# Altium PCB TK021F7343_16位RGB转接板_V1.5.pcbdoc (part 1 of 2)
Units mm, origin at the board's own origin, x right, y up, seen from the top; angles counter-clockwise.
Board outline 79.4 x 75.01 mm, 2 copper layers (Top Layer, Bottom Layer), stack 0.07 mm thick; 14 components, 33 nets, 105 pads, 145 vias.
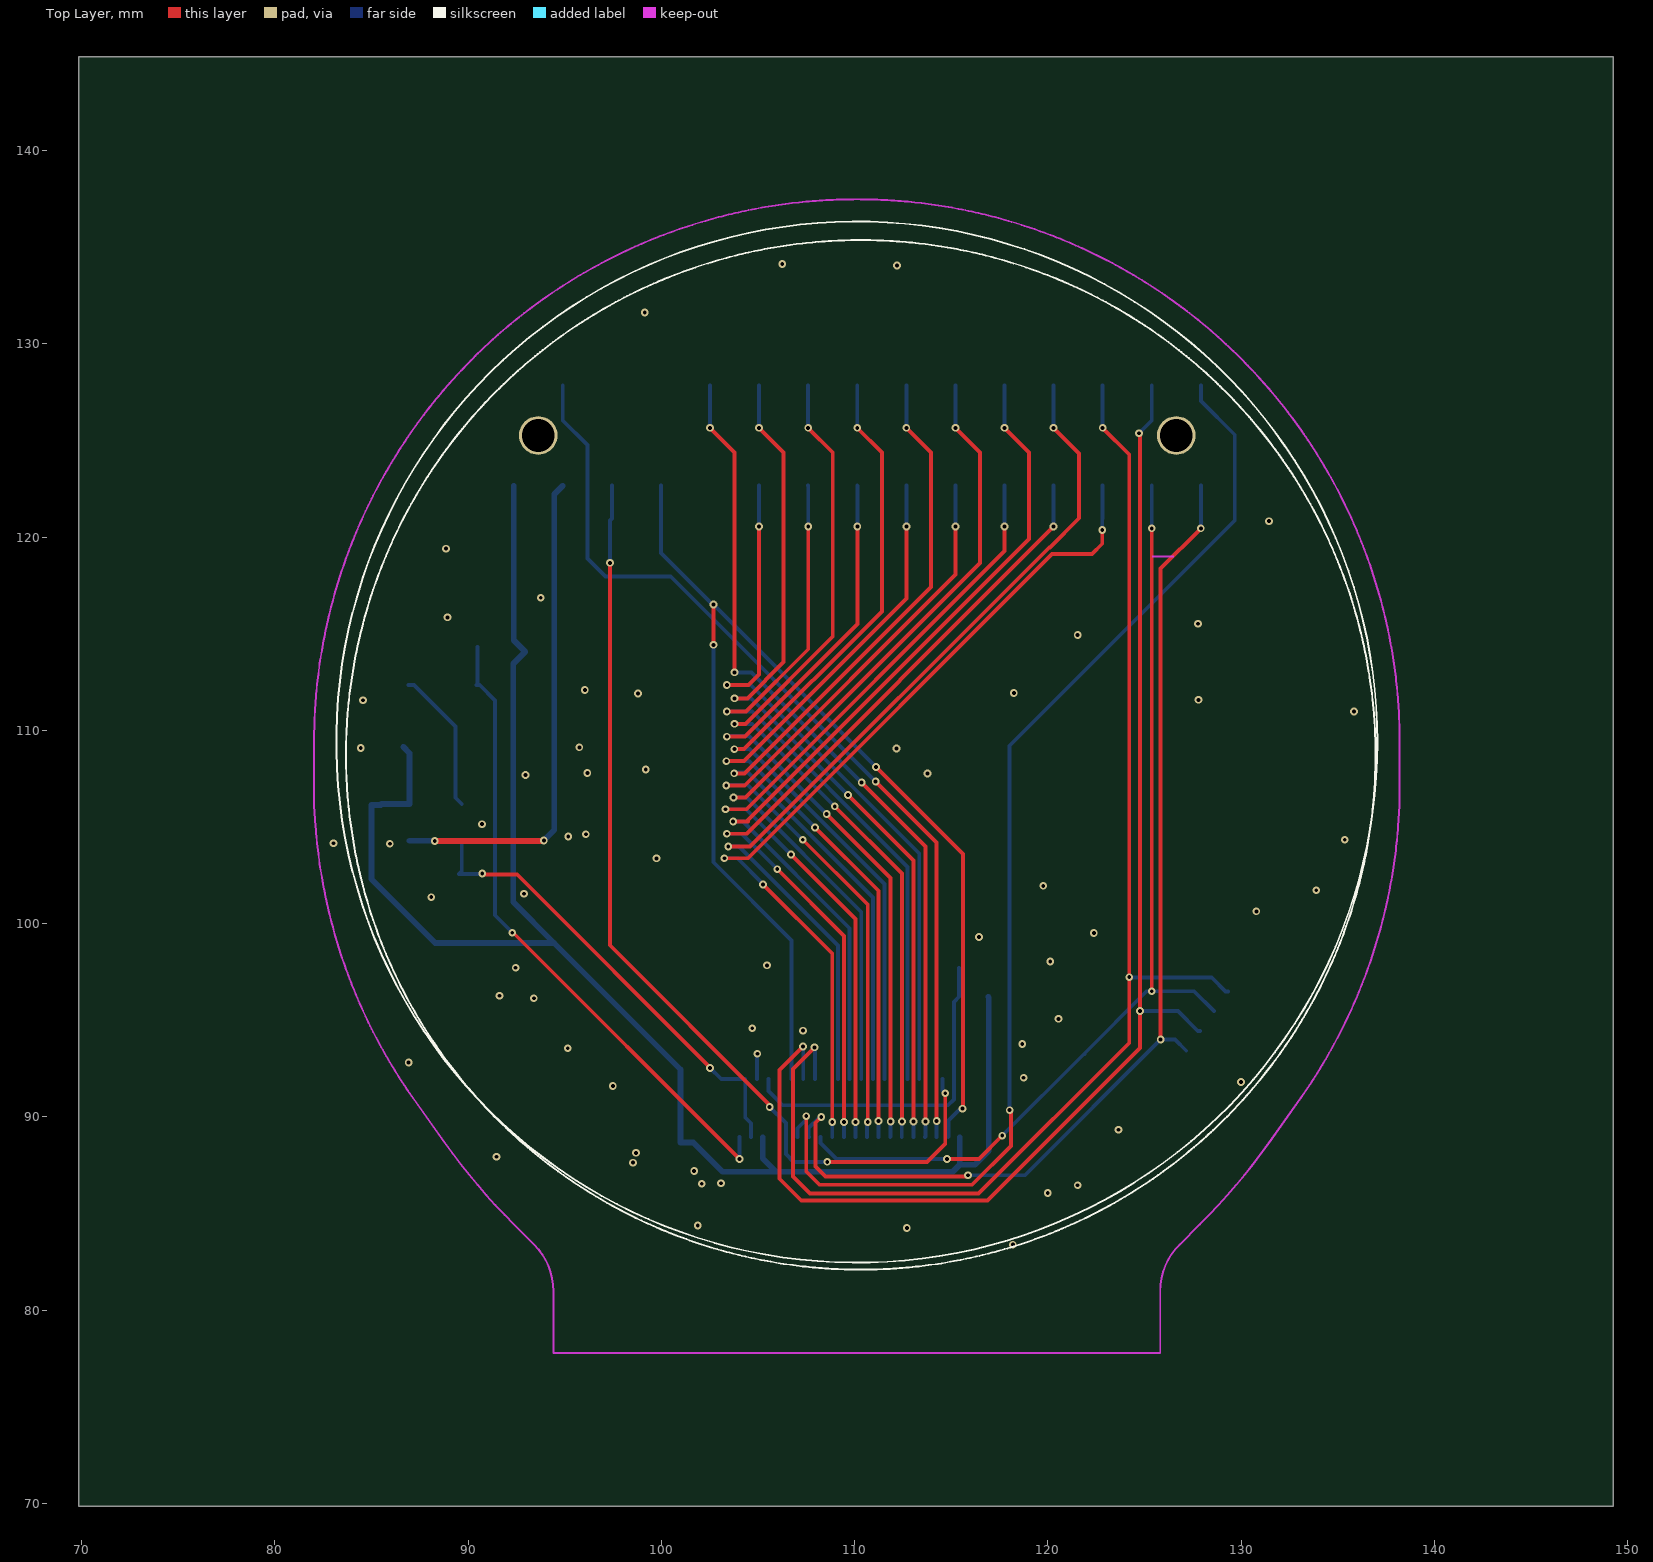
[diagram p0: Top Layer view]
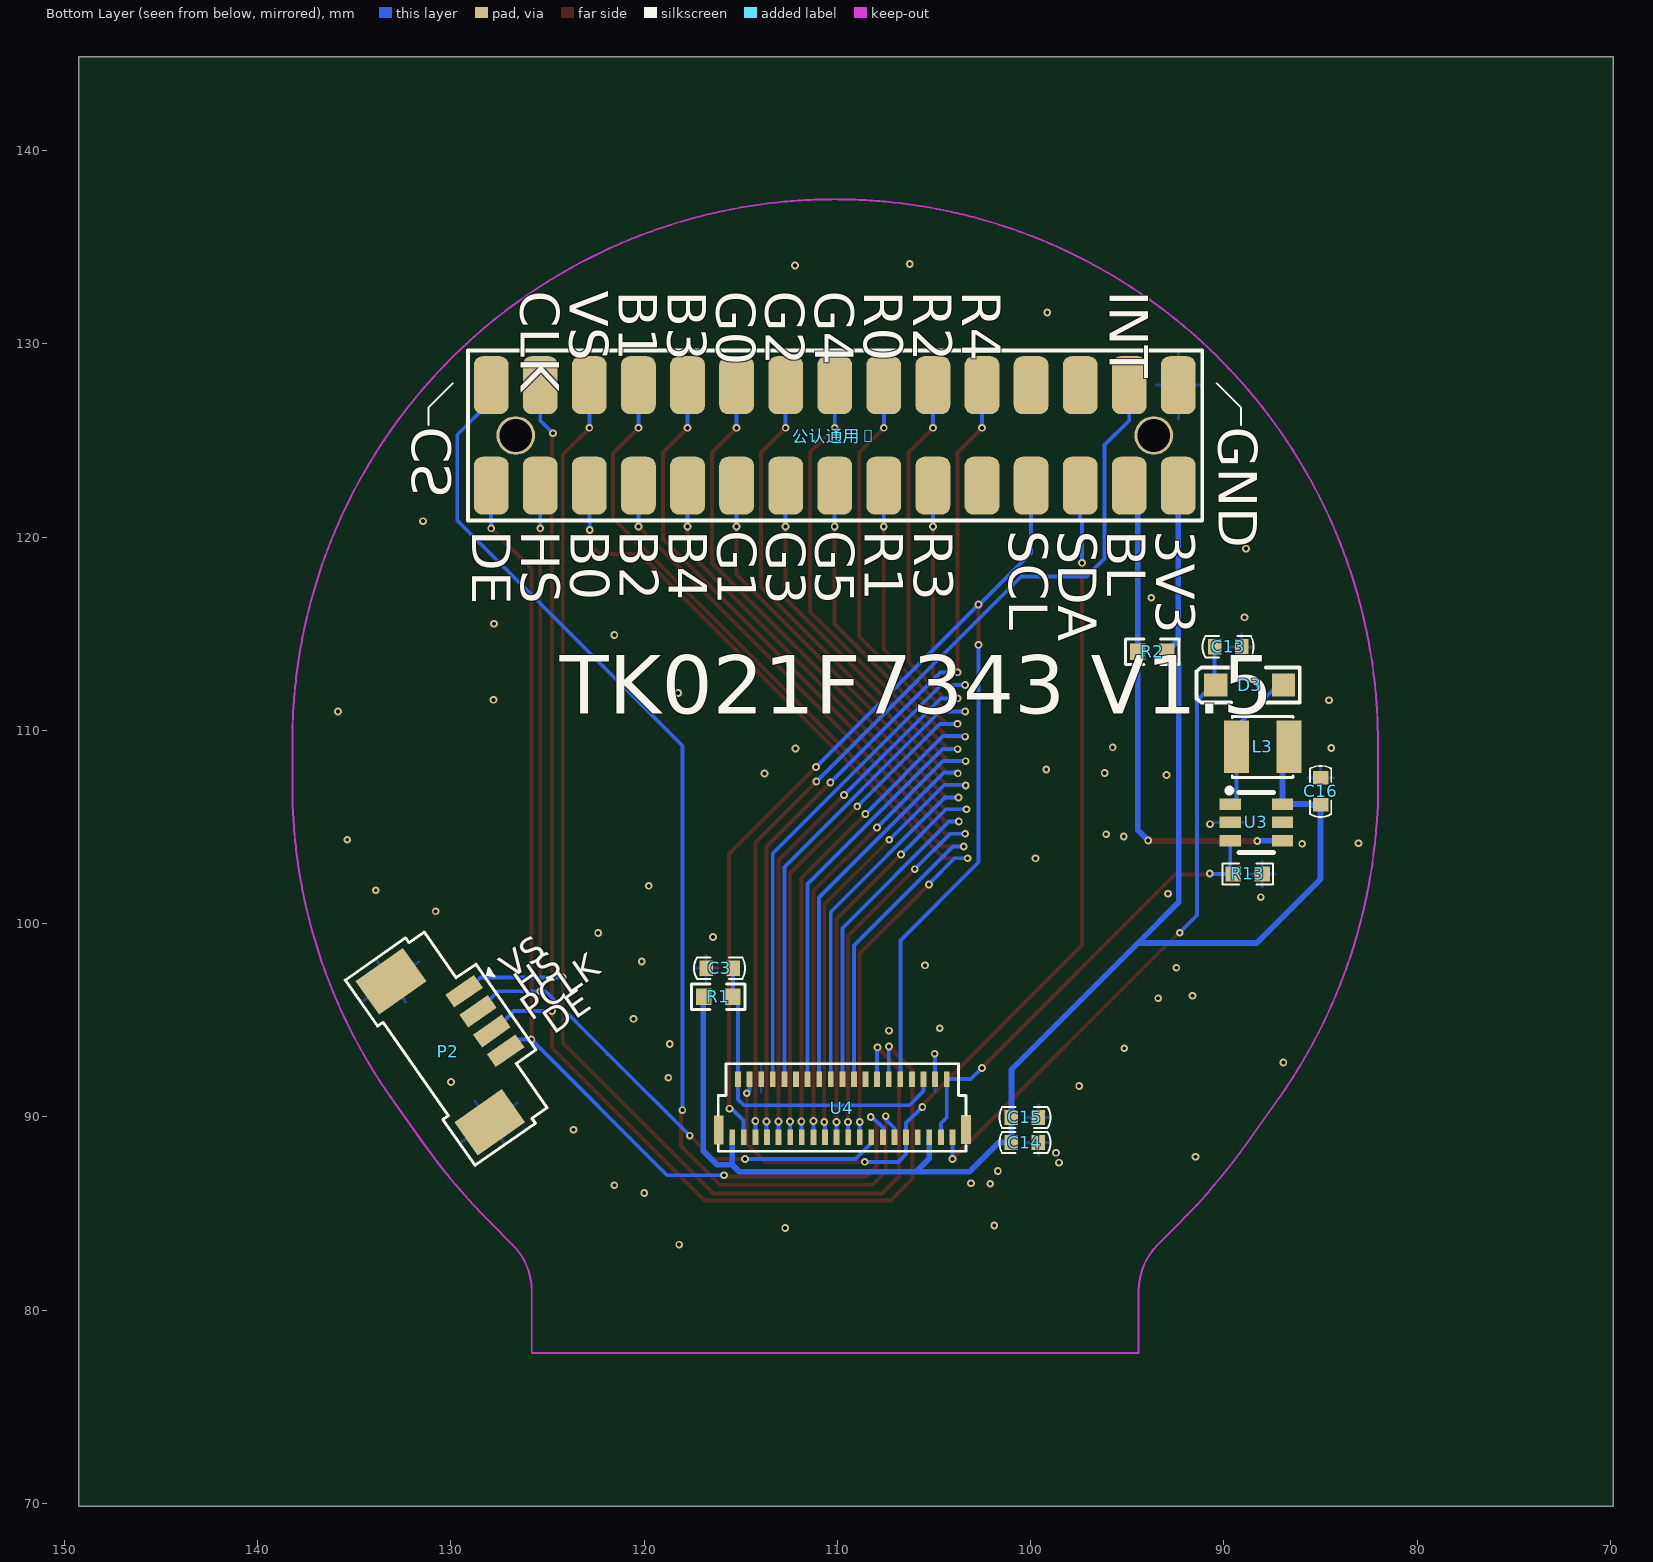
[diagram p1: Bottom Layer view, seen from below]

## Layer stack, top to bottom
Top Solder Mask Layer: solder mask 0.01, Dk 3.3
Top Layer: signal copper 0.035
Bottom Layer: signal copper 0.035
Bottom Solder Mask Layer: solder mask 0.01, Dk 3.3

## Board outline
149.25,69.85 69.85,69.85 69.85,144.856 149.25,144.856

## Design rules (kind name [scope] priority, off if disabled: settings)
BoardOutlineClearance Clearance [All] p0: genericclearance=0.254 ignorepadtopadclearanceinfootprint=FALSE except(0: Arc-SplitContinuation Track-SplitContinuation SMDPad-SplitContinuation THPad-SplitContinuation Via-SplitContinuation Fill-SplitContinuation Poly-SplitContinuation Region-SplitContinuation Text-SplitContinuation)
BoardOutlineClearance Clearance_Polygon [All] p0: genericclearance=0.254 ignorepadtopadclearanceinfootprint=FALSE except(0: Arc-SplitContinuation Track-SplitContinuation SMDPad-SplitContinuation THPad-SplitContinuation Via-SplitContinuation Fill-SplitContinuation Poly-SplitContinuation Region-SplitContinuation Text-SplitContinuation)
BoardOutlineClearance Plane_PlaneConnect [All] p0: genericclearance=0.254 ignorepadtopadclearanceinfootprint=FALSE except(0: Arc-SplitContinuation Track-SplitContinuation SMDPad-SplitContinuation THPad-SplitContinuation Via-SplitContinuation Fill-SplitContinuation Poly-SplitContinuation Region-SplitContinuation Text-SplitContinuation)
BoardOutlineClearance Copper_PolygonConnect [All] p0: genericclearance=0.254 ignorepadtopadclearanceinfootprint=FALSE except(0: Arc-SplitContinuation Track-SplitContinuation SMDPad-SplitContinuation THPad-SplitContinuation Via-SplitContinuation Fill-SplitContinuation Poly-SplitContinuation Region-SplitContinuation Text-SplitContinuation)
BoardOutlineClearance Copper_PolygonConnect_1 [All] p0: genericclearance=0.254 ignorepadtopadclearanceinfootprint=FALSE except(0: Arc-SplitContinuation Track-SplitContinuation SMDPad-SplitContinuation THPad-SplitContinuation Via-SplitContinuation Fill-SplitContinuation Poly-SplitContinuation Region-SplitContinuation Text-SplitContinuation)
BoardOutlineClearance otherClearance [All] p0: genericclearance=0.254 ignorepadtopadclearanceinfootprint=FALSE except(0: Arc-SplitContinuation Track-SplitContinuation SMDPad-SplitContinuation THPad-SplitContinuation Via-SplitContinuation Fill-SplitContinuation Poly-SplitContinuation Region-SplitContinuation Text-SplitContinuation)
Clearance [All] p1: gap=0.178 ignorepadtopadclearanceinfootprint=FALSE
Clearance Clearance_Polygon [All] p1: gap=0.178 ignorepadtopadclearanceinfootprint=FALSE
Clearance Plane_PlaneConnect [All] p1: gap=0.178 ignorepadtopadclearanceinfootprint=FALSE
Clearance Copper_PolygonConnect [All] p1: gap=0.178 ignorepadtopadclearanceinfootprint=FALSE
Clearance Copper_PolygonConnect_1 [All] p1: gap=0.178 ignorepadtopadclearanceinfootprint=FALSE
Clearance otherClearance [All] p1: gap=0.178 ignorepadtopadclearanceinfootprint=FALSE
DiffPairsRouting [All] p1: maxuncoupledlength=500 minlimit=5.9055 maxlimit=Infinity mostfreqgap=7.874 toplayer_minwidth=7.874 toplayer_prefwidth=7.874 toplayer_maxwidth=7.874 bottomlayer_minwidth=7.874 bottomlayer_prefwidth=7.874 bottomlayer_maxwidth=7.874
PolygonConnect [All] p1: connectstyle=Relief reliefentries=4 reliefconductorwidth=5.9055 polygonreliefangle="90 Angle" airgapwidth=10
PolygonConnect PolygonConnect_1 [All] p1: connectstyle=Direct reliefentries=4 reliefconductorwidth=10 polygonreliefangle="90 Angle" airgapwidth=10
RoutingVias [All] p1: viastyle="Through Hole" holewidth=7.874 minholewidth=7.874 maxholewidth=27.9922 width=7.874 minwidth=7.874 maxwidth=27.9922
SolderMaskExpansion [All] p1: useseparateexpansions=TRUE expansion=3.937 expansionbottom=3.937
Width [All] p1: maxlimit=16 minlimit=8 preferedwidth=8
2 further rules are at their usual default settings.

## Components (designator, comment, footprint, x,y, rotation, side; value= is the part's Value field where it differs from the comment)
C3 "" C0603 116.103,97.688 r0 bottom
C13 "" C0603-1 90.475,114.325 r180 bottom
C14 "" C0603-1 100.992,88.673 r180 bottom
C15 "" C0603-2 100.992,89.968 r180 bottom
C16 "" C0603-2 84.988,106.147 r90 bottom
D3 "" SOD123 86.918,112.348 r0 bottom
L3 "" IND-SMD_L3.0-W3.0_FNR30XXS 87.985,109.148 r0 bottom
P2 "" BHEADSMD1x4 129.311,96.495 r55 bottom
R1 "" R0603#1 116.154,96.215 r0 bottom
R2 "" R0603#1 93.701,114.071 r180 bottom
R13 "" R0603#2 89.509,102.569 r180 bottom
U3 "" SOT-23-6_L2.9-W1.6-P0.95-LS2.8-BR 88.315,105.236 r0 bottom
U4 "" TK021F7343-39P 103.784,92.634 r0 bottom
公认通用1 "" P_Head_2x15 127.912,127.864 r180 bottom

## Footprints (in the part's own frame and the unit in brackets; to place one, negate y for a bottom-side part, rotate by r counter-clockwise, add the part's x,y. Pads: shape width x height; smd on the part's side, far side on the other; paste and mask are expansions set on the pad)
BHEADSMD1x4 [mil]
  rect 32x71 smd: 1(0,0) 2(-49.21,0) 3(-98.43,0) 4(-147.64,0)
  rect 83x118 smd: 5(102.36,110.24) 6(-248.03,110.24)
  silkscreen extent -303,-68 158,185
C0603 [mm]
  rect 0.7x0.8 smd: 1(-0.712,-0.007) 2(0.688,-0.007)
  silkscreen extent -1.33,-0.56 1.31,0.54
C0603-1 [mm]
  rect 0.7x0.8 smd: 1(0,0) 2(1.4,0)
  silkscreen extent -0.62,-0.55 2.02,0.55
C0603-2 [mm]
  rect 0.7x0.8 smd: 1(0,0) 2(1.4,0)
  silkscreen extent -0.62,-0.55 2.02,0.55
IND-SMD_L3.0-W3.0_FNR30XXS [mm]
  rect 1.3x2.72 smd: 1(1.35,0) 2(-1.35,0)
  silkscreen extent -1.58,-1.58 1.58,1.58
P_Head_2x15 [mm]
  round 2 hole 1.7: 0(1.27,-2.6) 0(34.29,-2.6)
  rrect50% 1.8x3 smd: 1(0,0) 2(0,-5.2) 3(2.54,0) 4(2.54,-5.2) 5(5.08,0) 6(5.08,-5.2) 7(7.62,0) 8(7.62,-5.2) 9(10.16,0) 10(10.16,-5.2) 11(12.7,0) 12(12.7,-5.2) 13(15.24,0) 14(15.24,-5.2) 15(17.78,0) 16(17.78,-5.2) 17(20.32,0) 18(20.32,-5.2) 19(22.86,0) 20(22.86,-5.2) 21(25.4,0) 22(25.4,-5.2) 23(27.94,0) 24(27.94,-5.2) 25(30.48,0) 26(30.48,-5.2) 27(33.02,0) 28(33.02,-5.2) 29(35.56,0) 30(35.56,-5.2)
  silkscreen extent -1.2,-7 36.8,1.8
R0603#1 [mm]
  rect 0.806x0.864 smd: 1(-0.753,0) 2(0.753,0)
  silkscreen extent -1.39,-0.66 1.39,0.66
R0603#2 [mm]
  rect 0.8x0.8 smd: 1(0,0) 2(1.5,0)
  silkscreen extent -0.55,-0.55 2.05,0.55
SOD123 [mm]
  rect 1.2x1.2 smd: 1(0,0) 2(3.5,0)
  silkscreen extent -0.85,-0.9 4.5,0.9
SOT-23-6_L2.9-W1.6-P0.95-LS2.8-BR [mm]
  rect 1.1x0.6 smd: 1(1.35,-0.95) 2(1.35,0) 3(1.35,0.95) 4(-1.35,0.95) 5(-1.35,0) 6(-1.35,-0.95)
  silkscreen extent -0.9,-1.78 1.52,1.55
TK021F7343-39P [mm]
  rect 0.5x1.5 smd: 0(-0.446,3.283) 0(12.354,3.302)
  rect 0.3x0.8 smd: 1(0.254,3.683) 2(0.554,0.683) 3(0.854,3.683) 4(1.154,0.683) 5(1.454,3.683) 6(1.754,0.683) 7(2.054,3.683) 8(2.354,0.683) 9(2.654,3.683) 10(2.954,0.683) 11(3.254,3.683) 12(3.554,0.683) 13(3.854,3.683) 14(4.154,0.683) 15(4.454,3.683) 16(4.754,0.683) 17(5.054,3.683) 18(5.354,0.683) 19(5.654,3.683) 20(5.954,0.683) 21(6.254,3.683) 22(6.554,0.683) 23(6.854,3.683) 24(7.154,0.683) 25(7.454,3.683) 26(7.754,0.683) 27(8.054,3.683) 28(8.354,0.683) 29(8.654,3.683) 30(8.954,0.683) 31(9.254,3.683) 32(9.554,0.683) 33(9.854,3.683) 34(10.154,0.683) 35(10.454,3.683) 36(10.754,0.683) 37(11.054,3.683) 38(11.354,0.683) 39(11.654,3.683)
  silkscreen extent -0.45,-0.12 12.38,4.41

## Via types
v1: diameter 0.4, hole 0.2, Top Layer to Bottom Layer, 145 vias

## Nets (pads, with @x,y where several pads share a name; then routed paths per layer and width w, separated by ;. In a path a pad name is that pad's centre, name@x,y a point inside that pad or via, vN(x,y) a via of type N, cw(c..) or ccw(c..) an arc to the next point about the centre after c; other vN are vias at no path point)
3.3V: C14.1 C15.1 C16.1 L3.2 R1.2 R2.2 U3.6 U4.5 U4.39 公认通用1.30 | length 86.4
  Bottom Layer w0.3: L3.2@86.635,109.148 86.965,108.818 U3.6@86.965,106.186 85.511,106.186 85.471,106.147 C16.1@84.988,106.147 84.988,102.311 88.299,99.001 94.446,99.001 ; 公认通用1.30@92.352,122.664 92.352,114.667 R2.2@92.947,114.071 92.329,113.453 92.329,101.117 94.446,99.001 ; U4.5@105.238,88.951 105.238,87.852 105.934,87.157 ; U4.39@115.438,88.951 115.438,87.524 ; R1.2@116.908,96.215 116.942,96.181 116.942,88.24 116.226,87.524 115.438,87.524 ; 94.446,99.001 100.992,92.455 C15.1@100.992,89.968 C14.1@100.992,88.673 101.642,88.673 103.158,87.157 105.934,87.157 ; 105.934,87.157 115.071,87.157 115.438,87.524
$1N16968: D3.1 L3.1 U3.1 | length 7.5
  Bottom Layer w0.2: D3.1@86.918,112.348 87.197,112.348 89.335,110.211 L3.1@89.335,109.148 89.335,106.517 U3.1@89.665,106.186
B0: U4.16
B1: U4.17 公认通用1.6 | length 46.4
  Top Layer w0.2: v1(103.256,103.383) 104.476,103.383 120.218,119.126 122.276,119.126 122.809,119.659 v1(122.809,120.371) ; v1(105.256,102.03) 108.839,98.448 v1(108.839,89.738)
  Bottom Layer w0.2: v1(103.256,103.383) 103.931,103.383 105.256,102.059 v1(105.256,102.03) ; U4.17@108.838,88.951 v1(108.839,89.738) ; v1(122.809,120.371) 122.809,120.941 122.832,120.964 公认通用1.6@122.832,122.664
B2: U4.18 公认通用1.7 | length 47.4
  Top Layer w0.2: v1(103.453,103.987) 104.584,103.987 120.073,119.476 120.1,119.465 121.615,120.98 121.615,124.333 v1(120.292,125.656)
  Bottom Layer w0.2: v1(103.453,103.987) 104.014,103.987 109.138,98.862 U4.18@109.138,91.951 ; v1(120.292,125.656) 公认通用1.7@120.292,127.864
B3: U4.19 公认通用1.8 | length 44.3
  Top Layer w0.2: v1(103.384,104.648) 104.394,104.648 v1(120.292,120.546) ; v1(105.994,102.819) 109.449,99.365 v1(109.449,89.738)
  Bottom Layer w0.2: v1(103.384,104.648) 104.165,104.648 v1(105.994,102.819) ; U4.19@109.438,88.951 109.438,89.728 v1(109.449,89.738) ; v1(120.292,120.546) 公认通用1.8@120.292,122.664
B4: U4.20 公认通用1.9 | length 46
  Top Layer w0.2: v1@103.785,105.282 104.393,105.282 ; 104.47,105.282 104.393,105.282 ; v1(117.752,125.656) 119.024,124.384 119.024,119.913 104.393,105.282
  Bottom Layer w0.2: v1(103.709,105.282) 104.217,105.282 109.738,99.761 U4.20@109.738,91.951 ; v1(117.752,125.656) 公认通用1.9@117.752,127.864
B5: U4.21 公认通用1.10 | length 43.7
  Top Layer w0.2: v1(103.311,105.921) 104.397,105.921 117.757,119.281 v1@117.757,120.396 ; v1(106.705,103.581) 110.038,100.248 v1(110.038,89.738)
  Bottom Layer w0.2: v1(103.311,105.921) 104.366,105.921 v1(106.705,103.581) ; U4.21@110.038,88.951 v1(110.038,89.738) ; 公认通用1.10@117.752,122.664 117.757,122.659 v1@117.757,120.396
  other v1: 117.757,120.546
BL_CTR: R2.1 U3.4 公认通用1.28 | length 25.7
  Top Layer w0.3: v1(88.269,104.28) 93.889,104.28 v1(93.915,104.306)
  Bottom Layer w0.3: U3.4@86.965,104.286 88.263,104.286 v1(88.269,104.28) ; v1(93.915,104.306) 94.454,104.845 R2.1@94.454,114.071 94.454,122.226 公认通用1.28@94.892,122.664
CS: U4.11 公认通用1.1 | length 60.8
  Top Layer w0.2: v1(107.493,90.037) 107.493,87.173 108.179,86.487 116.078,86.487 118.085,88.494 118.085,90.283 v1(118.02,90.348)
  Bottom Layer w0.2: U4.11@107.038,88.951 107.038,89.411 107.493,89.865 v1(107.493,90.037) ; v1(118.02,90.348) 118.02,109.206 129.667,120.853 129.667,125.298 127.912,127.053 公认通用1.1@127.912,127.864
G0: U4.22 公认通用1.11 | length 45.2
  Top Layer w0.2: v1(103.734,106.529) 104.345,106.529 116.484,118.669 116.484,124.384 v1(115.212,125.656)
  Bottom Layer w0.2: v1(103.734,106.529) 104.418,106.529 110.338,100.609 U4.22@110.338,91.951 ; v1(115.212,125.656) 公认通用1.11@115.212,127.864
G1: U4.23 公认通用1.12 | length 42.9
  Top Layer w0.2: v1(103.35,107.154) 104.309,107.154 115.217,118.062 v1@115.217,120.396 ; v1(107.314,104.343) 110.675,100.982 v1@110.675,89.74
  Bottom Layer w0.2: v1(103.35,107.154) 103.384,107.188 104.445,107.188 107.29,104.343 v1(107.314,104.343) ; U4.23@110.638,88.951 110.638,89.7 v1(110.677,89.738) ; 公认通用1.12@115.212,122.664 115.217,122.659 v1@115.217,120.396
  other v1: 115.217,120.546
G2: U4.24 公认通用1.13 | length 44.4
  Top Layer w0.2: v1(103.763,107.778) 104.298,107.778 113.944,117.424 113.944,124.384 v1(112.672,125.656)
  Bottom Layer w0.2: v1(103.763,107.778) 103.808,107.823 104.47,107.823 110.938,101.355 U4.24@110.938,91.951 ; v1(112.672,125.656) 公认通用1.13@112.672,127.864
G3: U4.25 公认通用1.14 | length 42.1
  Top Layer w0.2: v1(103.359,108.407) 104.267,108.407 112.677,116.817 v1@112.677,120.396 ; v1(107.95,104.978) 111.227,101.702 v1(111.227,89.789)
  Bottom Layer w0.2: v1(103.359,108.407) 104.521,108.407 v1(107.95,104.978) ; v1(111.227,89.789) 111.238,89.777 U4.25@111.238,88.951 ; 公认通用1.14@112.672,122.664 112.677,122.659 v1@112.677,120.396
  other v1: 112.677,120.546
G4: U4.26 公认通用1.15 | length 43.6
  Top Layer w0.2: v1(103.772,109.029) 104.28,109.029 111.404,116.154 111.404,124.384 v1(110.132,125.656)
  Bottom Layer w0.2: v1(103.772,109.029) 104.559,109.029 111.538,102.05 U4.26@111.538,91.951 ; v1(110.132,125.656) 公认通用1.15@110.132,127.864
G5: U4.27 公认通用1.16 | length 41.3
  Top Layer w0.2: v1(103.384,109.677) 104.318,109.677 110.137,115.496 v1@110.137,120.396 ; v1(108.548,105.677) 111.862,102.363 v1(111.862,89.764)
  Bottom Layer w0.2: v1(103.384,109.677) 103.41,109.703 104.522,109.703 v1(108.548,105.677) ; 公认通用1.16@110.132,122.664 110.137,122.659 v1@110.137,120.396 ; U4.27@111.838,88.951 111.862,88.974 v1(111.862,89.764)
  other v1: 110.137,120.546
GND: C3.2 C13.2 C14.2 C15.2 C16.2 P2.5 P2.6 R13.2 U3.2 U4.4 U4.34 公认通用1.29 | length 1.3
  Bottom Layer w0.2: U4.4@104.938,91.951 104.938,93.243 v1(104.964,93.269)
  other v1: 118.186,83.388 112.7,84.252 101.879,84.379 119.994,86.059 121.539,86.462 102.083,86.538 103.086,86.568 101.691,87.203 98.527,87.63 91.465,87.935 98.679,88.138 123.647,89.332 97.485,91.592 129.997,91.807 118.745,92.024 86.919,92.812 95.148,93.548 118.669,93.768 107.326,94.463 104.699,94.59 120.548,95.072 93.396,96.139 91.618,96.266 92.456,97.714 105.461,97.841 120.117,98.044 116.431,99.313 122.377,99.517 130.785,100.635 88.087,101.371 92.888,101.549 133.883,101.727 119.761,101.956 99.746,103.378 85.945,104.135 83.033,104.159 135.357,104.343 95.179,104.512 96.088,104.623 90.717,105.147 92.964,107.696 113.767,107.772 96.164,107.798 99.187,107.975 112.166,109.068 84.442,109.089 95.753,109.123 135.839,110.973 84.557,111.557 127.787,111.582 98.781,111.912 118.237,111.938 96.037,112.09 121.539,114.935 127.762,115.519 88.925,115.849 93.751,116.865 88.849,119.405 131.445,120.828 99.136,131.623 112.192,134.061 106.248,134.137
INT: U4.35 公认通用1.27 | length 48.9
  Top Layer w0.2: v1(111.086,107.354) 114.24,104.2 v1(114.24,89.789)
  Bottom Layer w0.2: 公认通用1.27@94.892,127.864 94.892,126.037 96.164,124.765 96.164,118.897 97.104,117.958 100.482,117.958 v1(111.086,107.354) ; U4.35@114.238,88.951 114.238,89.673 114.24,89.675 v1(114.24,89.789)
LED-: R13.1 U3.3 U4.2 U4.3 | length 24.2
  Top Layer w0.2: v1(90.729,102.591) 90.781,102.538 92.535,102.538 102.514,92.559 v1(102.514,92.532)
  Bottom Layer w0.2: U3.3@89.665,104.286 89.665,102.726 R13.1@89.509,102.569 90.708,102.569 v1(90.729,102.591) ; v1(102.514,92.532) 103.096,91.951 U4.2@104.338,91.951 104.338,89.972 104.638,89.672 U4.3@104.638,88.951
LEDA2: C13.1 D3.2 U4.1 | length 33.4
  Top Layer w0.2: v1(92.278,99.526) 92.333,99.526 v1(104.038,87.821)
  Bottom Layer w0.2: C13.1@90.475,114.325 90.475,112.405 D3.2@90.418,112.348 90.596,112.348 91.389,111.555 91.389,100.432 92.278,99.543 v1(92.278,99.526) ; v1(104.038,87.821) U4.1@104.038,88.951
R0: U4.28
R1: U4.29 公认通用1.17 | length 46
  Top Layer w0.2: v1(103.784,110.338) 104.343,110.338 108.864,114.859 108.864,124.384 v1(107.592,125.656) ; v1(108.966,106.07) 112.446,102.591 v1(112.446,89.764)
  Bottom Layer w0.2: v1(103.784,110.338) 104.699,110.338 v1(108.966,106.07) ; v1(107.592,125.656) 公认通用1.17@107.592,127.864 ; U4.29@112.438,88.951 112.438,89.756 v1(112.446,89.764)
R2: U4.30 公认通用1.18 | length 37.7
  Top Layer w0.2: v1(103.384,110.974) 104.37,110.974 107.597,114.201 v1@107.597,120.396
  Bottom Layer w0.2: v1(103.384,110.974) 104.697,110.974 112.738,102.933 U4.30@112.738,91.951 ; 公认通用1.18@107.592,122.664 107.597,122.659 v1@107.597,120.396
  other v1: 107.597,120.546
R3: U4.31 公认通用1.19 | length 45.2
  Top Layer w0.2: v1(103.784,111.658) 104.445,111.658 106.324,113.538 106.324,124.384 v1(105.052,125.656) ; v1(109.652,106.655) 113.038,103.268 v1(113.038,89.764)
  Bottom Layer w0.2: v1(103.784,111.658) 104.648,111.658 v1(109.652,106.655) ; v1(105.052,125.656) 公认通用1.19@105.052,127.864 ; U4.31@113.038,88.951 v1(113.038,89.764)
R4: U4.32 公认通用1.20 | length 36.9
  Top Layer w0.2: v1(103.384,112.344) 104.496,112.344 105.052,112.9 v1@105.052,120.396
  Bottom Layer w0.2: v1(103.384,112.344) 104.623,112.344 113.338,103.628 U4.32@113.338,91.951 ; v1@105.052,120.396 公认通用1.20@105.052,122.664
  other v1: 105.052,120.546
R5: U4.33 公认通用1.21 | length 44.1
  Top Layer w0.2: v1(102.512,125.656) 103.784,124.384 v1(103.784,113.005) ; v1(110.358,107.304) 113.665,103.997 v1(113.665,89.764)
  Bottom Layer w0.2: v1(102.512,125.656) 公认通用1.21@102.512,127.864 ; v1(103.784,113.005) 104.658,113.005 v1(110.358,107.304) ; U4.33@113.638,88.951 113.665,88.977 v1(113.665,89.764)
RST: C3.1 R1.1 U4.6 U4.38 | length 17.5
  Bottom Layer w0.2: U4.6@105.538,91.951 105.538,91.337 106.274,90.602 114.833,90.602 115.138,90.907 U4.38@115.138,91.951 115.138,95.953 R1.1@115.401,96.215 115.401,97.686 C3.1@115.391,97.695
SCL: U4.10 U4.37 公认通用1.24 | length 66.8
  Top Layer w0.2: v1(102.692,114.427) v1(102.692,116.51) ; v1(111.1,108.102) 115.595,103.607 115.595,90.444 v1(115.575,90.424)
  Bottom Layer w0.2: 公认通用1.24@99.972,122.664 99.972,119.179 102.641,116.51 v1(102.692,116.51) v1(111.1,108.102) ; v1(102.692,114.427) 102.692,103.175 106.738,99.129 U4.10@106.738,91.951 ; U4.37@114.838,88.951 114.861,88.973 114.861,89.816 115.468,90.424 v1(115.575,90.424)
SDA: U4.9 U4.36 公认通用1.26 | length 50.6
  Top Layer w0.2: v1(97.333,118.669) 97.333,98.884 105.6,90.616 v1(105.6,90.513) ; v1(108.577,87.673) 113.733,87.673 114.69,88.629 v1(114.69,91.22)
  Bottom Layer w0.2: v1(97.333,118.669) 97.333,120.865 97.432,120.964 公认通用1.26@97.432,122.664 ; v1(105.6,90.513) 106.438,89.674 U4.9@106.438,88.951 106.438,88.075 106.841,87.673 v1(108.577,87.673) ; U4.36@114.538,91.951 114.538,91.371 v1(114.69,91.22)
T_DE: P2.4 U4.13 公认通用1.2 | length 56.2
  Top Layer w0.2: v1(108.269,89.997) 107.97,89.698 107.97,87.432 108.483,86.919 115.797,86.919 v1(115.858,86.979) ; v1(125.832,94.005) 125.832,96.308 125.824,96.315 125.824,118.369 v1(127.912,120.456)
  Bottom Layer w0.2: U4.13@107.638,88.951 107.613,88.976 107.613,89.419 108.191,89.997 v1(108.269,89.997) ; v1(115.858,86.979) 118.806,86.979 v1(125.832,94.005) 126.578,94.005 P2.4@127.16,93.423 ; v1(127.912,120.456) 公认通用1.2@127.912,122.664
T_HSYNC: P2.2 U4.15 公认通用1.4 | length 51.2
  Top Layer w0.2: v1(114.783,87.822) 116.43,87.822 v1(117.635,89.027) ; v1(125.372,120.456) 125.372,96.504 v1(125.374,96.502)
  Bottom Layer w0.2: U4.15@108.238,88.951 108.238,88.647 109.064,87.822 v1(114.783,87.822) ; v1(117.635,89.027) 121.851,93.243 ; 121.895,93.243 121.851,93.243 ; v1(125.372,120.456) 公认通用1.4@125.372,122.664 ; P2.2@128.594,95.471 127.563,96.502 v1(125.374,96.502) 125.109,96.502 121.851,93.243
T_PCLK: P2.3 U4.12 公认通用1.3 | length 69.5
  Top Layer w0.2: v1(107.328,93.638) 106.118,92.429 106.118,86.797 107.236,85.68 107.254,85.68 107.26,85.674 116.865,85.674 124.765,93.574 v1(124.765,95.479) 124.765,125.324 v1(124.714,125.374)
  Bottom Layer w0.2: v1(107.328,93.638) 107.338,93.627 U4.12@107.338,91.951 ; v1(124.714,125.374) 125.372,126.032 公认通用1.3@125.372,127.864 ; v1(124.765,95.479) 126.724,95.479 127.756,94.447 P2.3@127.877,94.447
T_VSYNC: P2.1 U4.14 公认通用1.5 | length 69.8
  Top Layer w0.2: v1(107.925,93.599) 106.808,92.483 106.808,86.918 107.696,86.03 116.408,86.03 124.206,93.828 v1(124.206,97.231) 124.206,124.282 v1(122.832,125.656)
  Bottom Layer w0.2: v1(107.925,93.599) 107.938,93.585 U4.14@107.938,91.951 ; v1(122.832,125.656) 公认通用1.5@122.832,127.864 ; v1(124.206,97.231) 124.231,97.206 128.479,97.206 129.19,96.495 P2.1@129.311,96.495
pads on no net: U3.5 U4.0 U4.7 U4.8 公认通用1.0 公认通用1.22 公认通用1.23 公认通用1.25

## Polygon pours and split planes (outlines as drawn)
GND on Top Layer (solid, remove dead copper, pour order 0): 81.686,138.227 138.76,138.227 138.76,76.2 81.686,76.2
GND on Bottom Layer (solid, remove dead copper, pour order 2): 76.2,138.506 142.9,138.506 142.9,76.479 76.2,76.479

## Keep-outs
Top Layer:
  region: 125.424,119.05 126.493,119.05 126.493,118.971 125.424,118.971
